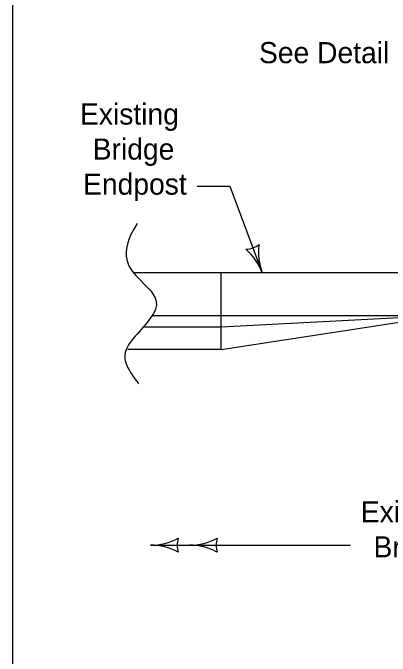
# Model space of a CAD drawing. Extents: x 10028 to 81668, y 3581 to 11018.
# Drawn here: x 20932.5 to 21204, y 8498.9 to 8961.7 of the extents above; entities that cross this region are included whole.
import ezdxf

# ---------------------------------------------------------------- set-up
doc = ezdxf.new("R2010")
doc.units = 0
for name, color, linetype in [('dsnCellsNorthArrow', 7, 'Continuous'), ('dsnTextTabulation', 7, 'Continuous'), ('Level 9', 7, 'Continuous'), ('SheetBorder', 7, 'Continuous')]:
    doc.layers.add(name, color=color, linetype=linetype)

msp = doc.modelspace()

# ---------------------------------------------------------------- linework, layer by layer
at = {"layer": 'dsnCellsNorthArrow'}
for p, q in [((21357.59, 8774.6), (21082.34, 8774.63)), ((21082.34, 8719.43), (21082.34, 8774.63)), ((21240.67, 8743.77), (21082.34, 8743.78)), ((21240.67, 8743.77), (21082.34, 8735.66)), ((21082.34, 8719.43), (21240.67, 8743.77))]:
    msp.add_line(p, q, dxfattribs=at)
at = {"layer": 'dsnTextTabulation'}
for p, q in [((21065.11, 8836.96), (21088.71, 8836.96)), ((21088.71, 8836.96), (21111.98, 8774.63)), ((21031.58, 8578.73), (21175.55, 8578.73))]:
    msp.add_line(p, q, dxfattribs=at)
for centre, radius, start, end in [((21099.52, 8808.01), 16.42, 272.7406, 308.2073), ((21151.8, 8789.49), 42.5, 172.4015, 200.4739), ((21072.17, 8759.76), 42.5, 20.4739, 48.5464), ((21031.58, 8621.23), 42.5, 270, 298.0725), ((21067.21, 8578.73), 16.42, 162.2666, 197.7334), ((21059.56, 8621.23), 42.5, 270, 298.0725), ((21095.2, 8578.73), 16.42, 162.2666, 197.7334), ((21031.58, 8536.23), 42.5, 61.9275, 90), ((21059.56, 8536.23), 42.5, 61.9275, 90)]:
    msp.add_arc(centre, radius, start, end, dxfattribs=at)
at = {"layer": 'Level 9'}
for p, q in [((21082.34, 8774.63), (21019.42, 8774.63)), ((21082.34, 8743.78), (21032.75, 8743.78)), ((21082.34, 8735.66), (21026.46, 8735.66)), ((21082.34, 8719.43), (21015.36, 8719.43))]:
    msp.add_line(p, q, dxfattribs=at)
msp.add_open_spline([(21022.07, 8810.2), (21006.99, 8787.12), (21025.62, 8767.59), (21044.26, 8750.72), (21008.76, 8720.53), (21015.62, 8704.3), (21022.32, 8695.77), (21023, 8694.93)], degree=3, dxfattribs=at)
at = {"layer": 'SheetBorder'}
msp.add_lwpolyline([(20932.52, 9944.02), (24067.53, 9944.02), (24067.53, 7924.02), (20932.52, 7924.02)], close=True, dxfattribs=at)

# ---------------------------------------------------------------- texts
at = {"layer": 'dsnCellsNorthArrow'}
for s, p in [("See Detail 'A'", (21109.66, 8925.51)), ('Existing', (20980.84, 8881.33)), ('Bridge', (20990, 8856.13)), ('Endpost', (20983.06, 8830.93)), ('Existing', (21182.93, 8595.13)), ('Bridge', (21192.09, 8569.93))]:
    msp.add_text(s, height=15.2, dxfattribs=at).set_placement(p)

doc.saveas('drawing.dxf')
